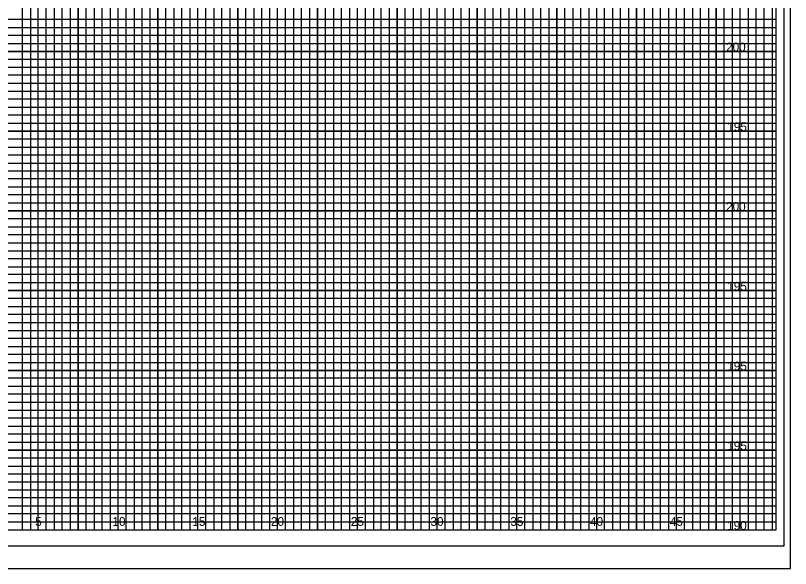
# Model space of a CAD drawing. Extents: x -4 to 103, y -2 to 351.
# Drawn here: x 54.82 to 103.4, y -2.43 to 32.25 of the extents above; entities that cross this region are included whole.
import ezdxf

# ---------------------------------------------------------------- set-up
doc = ezdxf.new("R2010")
doc.units = 0
for name, color, linetype in [('Old_Level_10', 7, 'Continuous'), ('Old_Level_16', 7, 'Continuous'), ('Old_Level_3', 7, 'Continuous'), ('Old_Level_4', 7, 'Continuous'), ('Old_Level_5', 7, 'Continuous'), ('Old_Level_6', 7, 'Continuous'), ('Old_Level_8', 7, 'Continuous'), ('Prop XS Finish Grade', 7, 'Continuous'), ('Prop XS SE Text', 7, 'Continuous')]:
    doc.layers.add(name, color=color, linetype=linetype)

msp = doc.modelspace()

# ---------------------------------------------------------------- linework, layer by layer
at = {"layer": 'Old_Level_10'}
for p, q in [((56.25, 0), (56.25, 65)), ((58.75, 0), (58.75, 65)), ((61.25, 0), (61.25, 65)), ((63.75, 0), (63.75, 65)), ((66.25, 0), (66.25, 65)), ((68.75, 0), (68.75, 65)), ((71.25, 0), (71.25, 65)), ((73.75, 0), (73.75, 65)), ((91.25, 0), (91.25, 63.425)), ((93.75, 0), (93.75, 63.425)), ((96.25, 0), (96.25, 63.425)), ((98.75, 0), (98.75, 63.425)), ((101.25, 0), (101.25, 63.425)), ((76.25, 0), (76.25, 62)), ((78.75, 0), (78.75, 62)), ((81.25, 0), (81.25, 62)), ((83.75, 0), (83.75, 62)), ((86.25, 0), (86.25, 62)), ((88.75, 0), (88.75, 62)), ((0, 30), (102.5, 30)), ((0, 27.5), (102.5, 27.5)), ((0, 25), (102.5, 25)), ((0, 22.5), (102.5, 22.5)), ((0, 20), (102.5, 20)), ((0, 17.5), (102.5, 17.5)), ((0, 15), (102.5, 15)), ((0, 12.5), (102.5, 12.5)), ((0, 10), (102.5, 10)), ((0, 7.5), (102.5, 7.5)), ((0, 5), (102.5, 5)), ((0, 2.5), (102.5, 2.5))]:
    msp.add_line(p, q, dxfattribs=at)
at = {"layer": 'Old_Level_3'}
msp.add_line((-3.5, -2.425), (102.1625, -2.425), dxfattribs=at)
at = {"layer": 'Old_Level_4'}
for points in [[(54.75, 0), (55.25, 0), (55.25, 65)], [(55.75, 65), (55.75, 0), (56.75, 0), (56.75, 65)], [(57.25, 65), (57.25, 0), (57.75, 0), (57.75, 65)], [(58.25, 65), (58.25, 0), (59.25, 0), (59.25, 65)], [(59.75, 65), (59.75, 0), (60.25, 0), (60.25, 65)], [(60.75, 65), (60.75, 0), (61.75, 0), (61.75, 65)], [(62.25, 65), (62.25, 0), (62.75, 0), (62.75, 65)], [(63.25, 65), (63.25, 0), (64.25, 0), (64.25, 65)], [(64.75, 65), (64.75, 0), (65.25, 0), (65.25, 65)], [(65.75, 65), (65.75, 0), (66.75, 0), (66.75, 65)], [(67.25, 65), (67.25, 0), (67.75, 0), (67.75, 65)], [(68.25, 65), (68.25, 0), (69.25, 0), (69.25, 65)], [(69.75, 65), (69.75, 0), (70.25, 0), (70.25, 65)], [(70.75, 65), (70.75, 0), (71.75, 0), (71.75, 65)], [(72.25, 65), (72.25, 0), (72.75, 0), (72.75, 65)], [(73.25, 65), (73.25, 0), (74.25, 0), (74.25, 62)], [(89.75, 62), (89.75, 0), (90.25, 0), (90.25, 63.425)], [(90.75, 63.425), (90.75, 0), (91.75, 0), (91.75, 63.425)], [(92.25, 63.425), (92.25, 0), (92.75, 0), (92.75, 63.425)], [(93.25, 63.425), (93.25, 0), (94.25, 0), (94.25, 63.425)], [(94.75, 63.425), (94.75, 0), (95.25, 0), (95.25, 63.425)], [(95.75, 63.425), (95.75, 0), (96.75, 0), (96.75, 63.425)], [(97.25, 63.425), (97.25, 0), (97.75, 0), (97.75, 63.425)], [(98.25, 63.425), (98.25, 0), (99.25, 0), (99.25, 63.425)], [(99.75, 63.425), (99.75, 0), (100.25, 0), (100.25, 63.425)], [(100.25, 63.425), (100.75, 63.425), (100.75, 0), (101.75, 0), (101.75, 63.425), (102.25, 63.425), (102.25, 0)], [(74.75, 62), (74.75, 0), (75.25, 0), (75.25, 62)], [(75.75, 62), (75.75, 0), (76.75, 0), (76.75, 62)], [(77.25, 62), (77.25, 0), (77.75, 0), (77.75, 62)], [(78.25, 62), (78.25, 0), (79.25, 0), (79.25, 62)], [(79.75, 62), (79.75, 0), (80.25, 0), (80.25, 62)], [(80.75, 62), (80.75, 0), (81.75, 0), (81.75, 62)], [(82.25, 62), (82.25, 0), (82.75, 0), (82.75, 62)], [(83.25, 62), (83.25, 0), (84.25, 0), (84.25, 62)], [(84.75, 62), (84.75, 0), (85.25, 0), (85.25, 62)], [(85.75, 62), (85.75, 0), (86.75, 0), (86.75, 62)], [(87.25, 62), (87.25, 0), (87.75, 0), (87.75, 62)], [(88.25, 62), (88.25, 0), (89.25, 0), (89.25, 62)], [(0, 31.5), (102.5, 31.5), (102.5, 32), (0, 32)], [(0, 30.5), (102.5, 30.5), (102.5, 31), (0, 31)], [(0, 29), (102.5, 29), (102.5, 29.5), (0, 29.5)], [(0, 28), (102.5, 28), (102.5, 28.5), (0, 28.5)], [(0, 26.5), (102.5, 26.5), (102.5, 27), (0, 27)], [(0, 25.5), (102.5, 25.5), (102.5, 26), (0, 26)], [(0, 24), (102.5, 24), (102.5, 24.5), (0, 24.5)], [(0, 23), (102.5, 23), (102.5, 23.5), (0, 23.5)], [(0, 21.5), (102.5, 21.5), (102.5, 22), (0, 22)], [(0, 20.5), (102.5, 20.5), (102.5, 21), (0, 21)], [(0, 19), (102.5, 19), (102.5, 19.5), (0, 19.5)], [(0, 18), (102.5, 18), (102.5, 18.5), (0, 18.5)], [(0, 16.5), (102.5, 16.5), (102.5, 17), (0, 17)], [(0, 15.5), (102.5, 15.5), (102.5, 16), (0, 16)], [(0, 14), (102.5, 14), (102.5, 14.5), (0, 14.5)], [(0, 13), (102.5, 13), (102.5, 13.5), (0, 13.5)], [(0, 11.5), (102.5, 11.5), (102.5, 12), (0, 12)], [(0, 10.5), (102.5, 10.5), (102.5, 11), (0, 11)], [(0, 9), (102.5, 9), (102.5, 9.5), (0, 9.5)], [(0, 8), (102.5, 8), (102.5, 8.5), (0, 8.5)], [(0, 6.5), (102.5, 6.5), (102.5, 7), (0, 7)], [(0, 5.5), (102.5, 5.5), (102.5, 6), (0, 6)], [(0, 4), (102.5, 4), (102.5, 4.5), (0, 4.5)], [(0, 3), (102.5, 3), (102.5, 3.5), (0, 3.5)], [(0, 1.5), (102.5, 1.5), (102.5, 2), (0, 2)], [(0, 0.5), (102.5, 0.5), (102.5, 1), (0, 1)]]:
    msp.add_lwpolyline(points, dxfattribs=at)
at = {"layer": 'Old_Level_5'}
msp.add_lwpolyline([(103.4, 67.4), (-3.5, 67.4), (-3.5, -2.425), (103.4, -2.425)], close=True, dxfattribs=at)
at = {"layer": 'Old_Level_6'}
msp.add_line((-3.5, -2.425), (103.4, -2.425), dxfattribs=at)
msp.add_lwpolyline([(102.5, 65), (0, 65), (0, 0), (102.5, 0)], close=True, dxfattribs=at)
at = {"layer": 'Old_Level_8'}
for points in [[(56.25, 0), (56.25, 65)], [(58.75, 65), (58.75, 0), (61.25, 0), (61.25, 65)], [(63.75, 65), (63.75, 0), (66.25, 0), (66.25, 65)], [(68.75, 65), (68.75, 0), (71.25, 0), (71.25, 65)], [(73.75, 65), (73.75, 0), (76.25, 0), (76.25, 62)], [(88.75, 62), (88.75, 0), (91.25, 0), (91.25, 63.425)], [(93.75, 63.425), (93.75, 0), (96.25, 0), (96.25, 63.425)], [(98.75, 63.425), (98.75, 0), (101.25, 0), (101.25, 63.425)], [(78.75, 62), (78.75, 0), (81.25, 0), (81.25, 62)], [(83.75, 62), (83.75, 0), (86.25, 0), (86.25, 62)], [(0, 27.5), (102.5, 27.5), (102.5, 30), (0, 30)], [(0, 22.5), (102.5, 22.5), (102.5, 25), (0, 25)], [(0, 17.5), (102.5, 17.5), (102.5, 20), (0, 20)], [(0, 12.5), (102.5, 12.5), (102.5, 15), (0, 15)], [(0, 7.5), (102.5, 7.5), (102.5, 10), (0, 10)], [(0, 2.5), (102.5, 2.5), (102.5, 5), (0, 5)]]:
    msp.add_lwpolyline(points, dxfattribs=at)
at = {"layer": 'Prop XS SE Text'}
msp.add_lwpolyline([(103, 66), (-2.8, 66), (-2.8, -1), (103, -1)], close=True, dxfattribs=at)

# ---------------------------------------------------------------- texts
at = {"layer": 'Old_Level_16'}
for s, p in [('5', (56.0574, 0.25)), ('10', (60.8971, 0.25)), ('15', (65.9057, 0.25)), ('20', (70.8312, 0.25)), ('25', (75.8399, 0.25)), ('30', (80.8312, 0.25)), ('35', (85.8399, 0.25)), ('40', (90.8313, 0.25)), ('45', (95.8399, 0.25))]:
    msp.add_text(s, height=0.55, dxfattribs=at).set_placement(p)
at = {"layer": 'Prop XS Finish Grade'}
for s, p in [('200', (99.3638, 30)), ('195', (99.4383, 25)), ('200', (99.3638, 20)), ('195', (99.4383, 15)), ('195', (99.4383, 10)), ('195', (99.4383, 5)), ('190', (99.4296, 0))]:
    msp.add_text(s, height=0.55, dxfattribs=at).set_placement(p)

doc.saveas('drawing.dxf')
